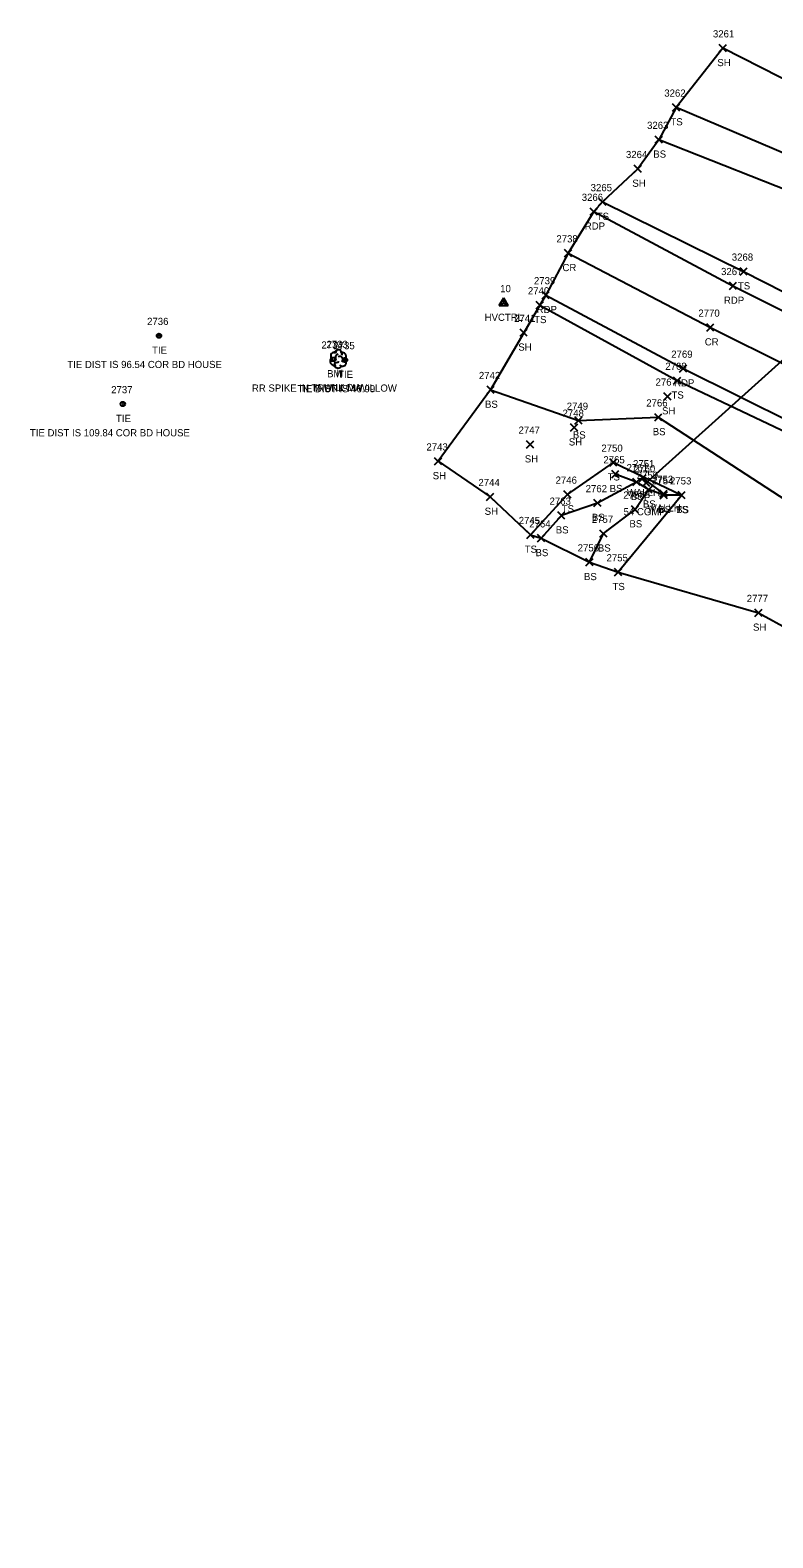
# Model space of a CAD drawing. Extents: x 1599569 to 1610055, y 642560 to 647860.
# Drawn here: x 1599569.2 to 1599776.3, y 647440.2 to 647860.2 of the extents above; entities that cross this region are included whole.
import ezdxf

# ---------------------------------------------------------------- set-up
doc = ezdxf.new("R2010")
doc.units = 0
for name, color, linetype in [('C_A', 7, 'Continuous'), ('C_C', 7, 'Continuous'), ('C_I', 7, 'Continuous'), ('CBP', 7, 'Continuous'), ('CPBM', 7, 'Continuous'), ('CPSM', 7, 'Continuous'), ('D_A', 7, 'Continuous'), ('D_C', 7, 'Continuous'), ('D_I', 7, 'Continuous'), ('D_TIC', 7, 'Continuous'), ('DCP', 7, 'Continuous'), ('DHW', 7, 'Continuous'), ('L_A', 7, 'Continuous'), ('L_C', 7, 'Continuous'), ('L_I', 7, 'Continuous'), ('L_TIC', 7, 'Continuous'), ('LELB', 7, 'Continuous'), ('LSOGP', 7, 'Continuous'), ('LTD', 7, 'Continuous'), ('P_A', 7, 'Continuous'), ('P_I', 7, 'Continuous'), ('P_TIC', 7, 'Continuous'), ('PET', 7, 'Continuous'), ('PRC', 7, 'Continuous')]:
    doc.layers.add(name, color=color, linetype=linetype)

msp = doc.modelspace()

# ---------------------------------------------------------------- linework, layer by layer
at = {"layer": 'CBP'}
for centre, radius in [((1599605.15, 647775.05), 0.625), ((1599605.15, 647775.05), 0.0833), ((1599657.03, 647768.3), 0.625), ((1599657.03, 647768.3), 0.0833), ((1599595.09, 647756.03), 0.625), ((1599595.09, 647756.03), 0.0833)]:
    msp.add_circle(centre, radius, dxfattribs=at)
at = {"layer": 'CPBM'}
for p, q in [((1599653.2, 647767.98), (1599653.2, 647768.98)), ((1599653.2, 647768.98), (1599654.2, 647768.98)), ((1599654.2, 647767.98), (1599653.2, 647767.98)), ((1599653.7, 647768.48), (1599653.7, 647768.48)), ((1599653.7, 647768.48), (1599653.7, 647768.48)), ((1599654.2, 647768.98), (1599654.2, 647767.98))]:
    msp.add_line(p, q, dxfattribs=at)
at = {"layer": 'CPSM'}
for p, q in [((1599700.01, 647783.46), (1599701.26, 647785.63)), ((1599702.51, 647783.46), (1599701.26, 647785.63)), ((1599701.26, 647784.19), (1599701.26, 647785.63)), ((1599700.01, 647783.46), (1599701.26, 647784.19)), ((1599700.01, 647783.46), (1599702.51, 647783.46)), ((1599701.26, 647784.19), (1599701.26, 647784.19)), ((1599701.26, 647784.19), (1599702.51, 647783.46))]:
    msp.add_line(p, q, dxfattribs=at)
at = {"layer": 'D_TIC'}
for points in [[(1599739.02, 647734.4), (1599741.02, 647736.4)], [(1599741.02, 647734.4), (1599739.02, 647736.4)], [(1599739.96, 647733.04), (1599741.96, 647735.04)], [(1599741.96, 647733.04), (1599739.96, 647735.04)], [(1599744.81, 647730.06), (1599746.81, 647732.06)], [(1599746.81, 647730.06), (1599744.81, 647732.06)]]:
    msp.add_lwpolyline(points, dxfattribs=at)
at = {"layer": 'DCP'}
msp.add_lwpolyline([(1599740.96, 647734.04), (1599814.69, 647800.27)], dxfattribs=at)
at = {"layer": 'DHW'}
msp.add_lwpolyline([(1599740.02, 647735.4), (1599745.81, 647731.06)], dxfattribs=at)
at = {"layer": 'L_TIC'}
for points in [[(1599761.33, 647854.15), (1599763.33, 647856.15)], [(1599763.33, 647854.15), (1599761.33, 647856.15)], [(1599748.34, 647837.65), (1599750.34, 647839.65)], [(1599750.34, 647837.65), (1599748.34, 647839.65)], [(1599743.53, 647828.66), (1599745.53, 647830.66)], [(1599745.53, 647828.66), (1599743.53, 647830.66)], [(1599737.64, 647820.54), (1599739.64, 647822.54)], [(1599739.64, 647820.54), (1599737.64, 647822.54)], [(1599727.81, 647811.31), (1599729.81, 647813.31)], [(1599729.81, 647811.31), (1599727.81, 647813.31)], [(1599767.15, 647791.96), (1599769.15, 647793.96)], [(1599769.15, 647791.96), (1599767.15, 647793.96)], [(1599710.35, 647782.57), (1599712.35, 647784.57)], [(1599712.35, 647782.57), (1599710.35, 647784.57)], [(1599705.84, 647774.9), (1599707.84, 647776.9)], [(1599707.84, 647774.9), (1599705.84, 647776.9)], [(1599748.63, 647761.55), (1599750.63, 647763.55)], [(1599750.63, 647761.55), (1599748.63, 647763.55)], [(1599696.61, 647758.98), (1599698.61, 647760.98)], [(1599698.61, 647758.98), (1599696.61, 647760.98)], [(1599745.91, 647757.15), (1599747.91, 647759.15)], [(1599747.91, 647757.15), (1599745.91, 647759.15)], [(1599721.1, 647750.43), (1599723.1, 647752.43)], [(1599723.1, 647750.43), (1599721.1, 647752.43)], [(1599743.36, 647751.34), (1599745.36, 647753.34)], [(1599745.36, 647751.34), (1599743.36, 647753.34)], [(1599719.92, 647748.48), (1599721.92, 647750.48)], [(1599721.92, 647748.48), (1599719.92, 647750.48)], [(1599707.65, 647743.76), (1599709.65, 647745.76)], [(1599709.65, 647743.76), (1599707.65, 647745.76)], [(1599681.98, 647739.08), (1599683.98, 647741.08)], [(1599683.98, 647739.08), (1599681.98, 647741.08)], [(1599730.83, 647738.74), (1599732.83, 647740.74)], [(1599732.83, 647738.74), (1599730.83, 647740.74)], [(1599731.36, 647735.5), (1599733.36, 647737.5)], [(1599733.36, 647735.5), (1599731.36, 647737.5)], [(1599737.27, 647733.3), (1599739.27, 647735.3)], [(1599739.27, 647733.3), (1599737.27, 647735.3)], [(1599737.27, 647733.3), (1599739.27, 647735.3)], [(1599739.27, 647733.3), (1599737.27, 647735.3)], [(1599696.47, 647729.17), (1599698.47, 647731.17)], [(1599698.47, 647729.17), (1599696.47, 647731.17)], [(1599718.04, 647729.84), (1599720.04, 647731.84)], [(1599720.04, 647729.84), (1599718.04, 647731.84)], [(1599740.61, 647731.19), (1599742.61, 647733.19)], [(1599742.61, 647731.19), (1599740.61, 647733.19)], [(1599740.61, 647731.19), (1599742.61, 647733.19)], [(1599742.61, 647731.19), (1599740.61, 647733.19)], [(1599744.91, 647729.65), (1599746.91, 647731.65)], [(1599746.91, 647729.65), (1599744.91, 647731.65)], [(1599749.88, 647729.63), (1599751.88, 647731.63)], [(1599751.88, 647729.63), (1599749.88, 647731.63)], [(1599749.88, 647729.63), (1599751.88, 647731.63)], [(1599751.88, 647729.63), (1599749.88, 647731.63)], [(1599716.34, 647723.98), (1599718.34, 647725.98)], [(1599718.34, 647723.98), (1599716.34, 647725.98)], [(1599726.41, 647727.46), (1599728.41, 647729.46)], [(1599728.41, 647727.46), (1599726.41, 647729.46)], [(1599736.87, 647725.67), (1599738.87, 647727.67)], [(1599738.87, 647725.67), (1599736.87, 647727.67)], [(1599707.71, 647718.6), (1599709.71, 647720.6)], [(1599709.71, 647718.6), (1599707.71, 647720.6)], [(1599710.69, 647717.65), (1599712.69, 647719.65)], [(1599712.69, 647717.65), (1599710.69, 647719.65)], [(1599728.08, 647718.93), (1599730.08, 647720.93)], [(1599730.08, 647718.93), (1599728.08, 647720.93)], [(1599724.19, 647710.97), (1599726.19, 647712.97)], [(1599726.19, 647710.97), (1599724.19, 647712.97)], [(1599732.19, 647708.2), (1599734.19, 647710.2)], [(1599734.19, 647708.2), (1599732.19, 647710.2)], [(1599771.28, 647696.88), (1599773.28, 647698.88)], [(1599773.28, 647696.88), (1599771.28, 647698.88)]]:
    msp.add_lwpolyline(points, dxfattribs=at)
at = {"layer": 'LELB'}
for points in [[(1599867.62, 647815.31), (1599840.36, 647815.31), (1599822.81, 647817.81), (1599792.8, 647820.18), (1599749.34, 647838.65)], [(1599810.07, 647804.55), (1599788.24, 647812.38), (1599744.53, 647829.66)], [(1599728.81, 647812.31), (1599768.15, 647792.96), (1599808.19, 647772.58), (1599853.49, 647751.31), (1599896.91, 647732.66), (1599944.27, 647711.3), (1599995.07, 647690.25), (1600038.53, 647673.11), (1600069.53, 647660.63), (1600111.66, 647644.91), (1600147.02, 647631.01), (1600185.01, 647616.1), (1600232.31, 647597.96), (1600265.15, 647585.19), (1600308.36, 647569.24), (1600357.09, 647550.14)], [(1599711.35, 647783.57), (1599749.63, 647762.55), (1599796.65, 647740.26), (1599833.67, 647721.94), (1599877.39, 647702.39), (1599924.86, 647682.37), (1599972.59, 647663.51), (1600011.34, 647647.51), (1600055.84, 647629.73), (1600100.47, 647612.9)], [(1599697.61, 647759.98), (1599722.1, 647751.43), (1599744.36, 647752.34), (1599789.18, 647723.21), (1599824.42, 647706.1), (1599868.39, 647681.04), (1599912.82, 647658.19), (1599958.42, 647634.17), (1599997.43, 647618.28), (1600043.89, 647603.78), (1600086.31, 647587.76), (1600138.43, 647576.08), (1600182.57, 647557.27), (1600228.03, 647536.75), (1600266.38, 647516.33), (1600313.23, 647498.51), (1600354.12, 647480.34), (1600399.45, 647460.99), (1600449.42, 647451.6), (1600497.01, 647440.19)], [(1599708.71, 647719.6), (1599719.04, 647730.84), (1599731.83, 647739.74), (1599750.88, 647730.63), (1599733.19, 647709.2)], [(1599725.19, 647711.97), (1599729.08, 647719.93), (1599737.87, 647726.67), (1599741.61, 647732.19), (1599738.27, 647734.3), (1599727.41, 647728.46), (1599717.34, 647724.98), (1599711.69, 647718.65)], [(1599738.27, 647734.3), (1599732.36, 647736.5)], [(1599750.88, 647730.63), (1599745.91, 647730.65), (1599741.61, 647732.19)]]:
    msp.add_lwpolyline(points, dxfattribs=at)
at = {"layer": 'LSOGP'}
msp.add_lwpolyline([(1599799.23, 647836.38), (1599762.33, 647855.15), (1599749.35, 647838.65), (1599744.54, 647829.66), (1599738.65, 647821.54), (1599728.81, 647812.31), (1599726.39, 647809.62), (1599719.21, 647798.06), (1599712.97, 647786.38), (1599711.35, 647783.57), (1599706.85, 647775.89), (1599697.61, 647759.98), (1599682.98, 647740.08), (1599697.47, 647730.17), (1599708.71, 647719.6), (1599711.69, 647718.65), (1599725.2, 647711.96), (1599733.19, 647709.2), (1599772.28, 647697.88), (1599807.65, 647678.52)], dxfattribs=at)
at = {"layer": 'LTD'}
msp.add_line((1599655.1, 647768.64), (1599655.1, 647768.64), dxfattribs=at)
msp.add_line((1599655.1, 647768.64), (1599655.1, 647768.64), dxfattribs=at)
msp.add_arc((1599655.14, 647770.07), 1.05, 335.5272, 180.9563, dxfattribs=at)
for centre, major_axis, ratio, start_param, end_param in [((1599654.01, 647767.93), (0.58, -1.04), 0.959034, 3.141593, 6.283185), ((1599654.31, 647769.3), (1.21, -0.51), 0.895232, 1.570796, 4.712389), ((1599654.64, 647767.89), (-0.625, -0.083), 0.423636, 0, 3.141593), ((1599654.89, 647769.09), (-0.208, -0.792), 0.645439, 3.141593, 6.283185), ((1599655.6, 647768.47), (-0.5, 0.667), 0.989748, 3.141593, 6.283185), ((1599656.1, 647767.8), (-1.09, 0.79), 0.841452, 1.570796, 4.712389), ((1599656.14, 647769.22), (-1.14, -0.48), 0.949671, 1.570796, 4.712389), ((1599655.1, 647767.14), (0.26, 1.06), 0.942809, 1.570796, 4.712389)]:
    msp.add_ellipse(centre, major_axis=major_axis, ratio=ratio, start_param=start_param, end_param=end_param, dxfattribs=at)
at = {"layer": 'P_TIC'}
for points in [[(1599725.38, 647808.62), (1599727.38, 647810.62)], [(1599727.38, 647808.62), (1599725.38, 647810.62)], [(1599718.21, 647797.05), (1599720.21, 647799.05)], [(1599720.21, 647797.05), (1599718.21, 647799.05)], [(1599764.17, 647787.95), (1599766.17, 647789.95)], [(1599766.17, 647787.95), (1599764.17, 647789.95)], [(1599711.97, 647785.38), (1599713.97, 647787.38)], [(1599713.97, 647785.38), (1599711.97, 647787.38)], [(1599757.87, 647776.36), (1599759.87, 647778.36)], [(1599759.87, 647776.36), (1599757.87, 647778.36)], [(1599750.28, 647764.92), (1599752.28, 647766.92)], [(1599752.28, 647764.92), (1599750.28, 647766.92)]]:
    msp.add_lwpolyline(points, dxfattribs=at)
at = {"layer": 'PET'}
for points in [[(1599726.38, 647809.62), (1599765.17, 647788.95), (1599807.03, 647767.98), (1599850.85, 647747.24), (1599895.21, 647727.77), (1599941.94, 647707.82), (1599994.49, 647686.81), (1600037.05, 647669.82), (1600068.7, 647657.7), (1600109.97, 647641.43), (1600146.07, 647627.29), (1600183.44, 647612.79), (1600231.32, 647594.52), (1600263.07, 647581.81), (1600307.68, 647564.32), (1600354.99, 647546.03)], [(1599712.97, 647786.38), (1599751.28, 647765.92), (1599797.63, 647742.86), (1599835.45, 647724.57), (1599878.46, 647705.28), (1599926.24, 647684.77), (1599973.4, 647665.7), (1600012.45, 647650.07), (1600057, 647632.55), (1600100.87, 647615.07)]]:
    msp.add_lwpolyline(points, dxfattribs=at)
at = {"layer": 'PRC'}
msp.add_lwpolyline([(1599719.21, 647798.05), (1599758.87, 647777.36), (1599802.99, 647755.44), (1599842.26, 647736.45), (1599884.02, 647718.08), (1599932.1, 647697.56), (1599978.21, 647679.31), (1600018.18, 647663.4), (1600061.65, 647646.14), (1600106.08, 647628.64)], dxfattribs=at)

# ---------------------------------------------------------------- texts
at = {"layer": 'C_A'}
for s, p in [('HVCTRL', (1599695.95, 647779.19)), ('TIE', (1599603.23, 647770.05)), ('BM', (1599652.02, 647763.48)), ('TIE', (1599655.11, 647763.3)), ('TIE', (1599593.17, 647751.03))]:
    msp.add_text(s, height=2, dxfattribs=at).set_placement(p)
at = {"layer": 'C_C'}
for s, p in [('TIE DIST IS 96.54 COR BD HOUSE', (1599579.59, 647766.05)), ('RR SPIKE IN TRUNK M WILLOW', (1599631.06, 647759.48)), ('TIE DIST IS 46.99', (1599643.73, 647759.3)), ('TIE DIST IS 109.84 COR BD HOUSE', (1599569.17, 647747.03))]:
    msp.add_text(s, height=2, dxfattribs=at).set_placement(p)
at = {"layer": 'C_I'}
for s, p in [('10', (1599700.27, 647787.19)), ('2736', (1599601.84, 647778.05)), ('2734', (1599650.44, 647771.48)), ('2735', (1599653.77, 647771.3)), ('2737', (1599591.83, 647759.03))]:
    msp.add_text(s, height=2, dxfattribs=at).set_placement(p)
at = {"layer": 'D_A'}
for s, p in [('WALLH', (1599735.61, 647730.4)), ('P', (1599740.34, 647729.04)), ('WALLH', (1599741.4, 647726.06))]:
    msp.add_text(s, height=2, dxfattribs=at).set_placement(p)
at = {"layer": 'D_C'}
msp.add_text('54 CGMP', height=2, dxfattribs=at).set_placement((1599734.68, 647725.04))
at = {"layer": 'D_I'}
for s, p in [('2751', (1599737.32, 647738.4)), ('2760', (1599737.56, 647737.04)), ('2752', (1599742.55, 647734.06))]:
    msp.add_text(s, height=2, dxfattribs=at).set_placement(p)
at = {"layer": 'L_A'}
for s, p in [('SH', (1599760.82, 647850.15)), ('TS', (1599747.75, 647833.65)), ('BS', (1599742.97, 647824.66)), ('SH', (1599737.13, 647816.54)), ('TS', (1599727.21, 647807.31)), ('TS', (1599766.56, 647787.96)), ('TS', (1599709.76, 647778.57)), ('SH', (1599705.33, 647770.9)), ('H', (1599654.53, 647763.64)), ('TS', (1599748.04, 647757.55)), ('BS', (1599696.05, 647754.98)), ('SH', (1599745.4, 647753.15)), ('BS', (1599720.54, 647746.43)), ('BS', (1599742.81, 647747.34)), ('SH', (1599719.41, 647744.48)), ('SH', (1599707.14, 647739.76)), ('SH', (1599681.47, 647735.08)), ('TS', (1599730.24, 647734.74)), ('BS', (1599730.8, 647731.5)), ('BS', (1599736.71, 647729.3)), ('BS', (1599736.71, 647729.3)), ('SH', (1599695.96, 647725.17)), ('TS', (1599717.45, 647725.84)), ('BS', (1599740.05, 647727.19)), ('BS', (1599740.05, 647727.19)), ('BS', (1599744.35, 647725.65)), ('TS', (1599749.28, 647725.63)), ('BS', (1599749.32, 647725.63)), ('BS', (1599715.78, 647719.98)), ('BS', (1599725.85, 647723.46)), ('BS', (1599736.31, 647721.67)), ('TS', (1599707.12, 647714.6)), ('BS', (1599710.13, 647713.65)), ('BS', (1599727.52, 647714.93)), ('BS', (1599723.64, 647706.97)), ('TS', (1599731.6, 647704.2)), ('SH', (1599770.77, 647692.88))]:
    msp.add_text(s, height=2, dxfattribs=at).set_placement(p)
at = {"layer": 'L_C'}
msp.add_text('M WILLOW', height=2, dxfattribs=at).set_placement((1599648.04, 647759.64))
at = {"layer": 'L_I'}
for s, p in [('3261', (1599759.59, 647858.15)), ('3262', (1599746.03, 647841.65)), ('3263', (1599741.23, 647832.66)), ('3264', (1599735.34, 647824.54)), ('3265', (1599725.5, 647815.31)), ('3268', (1599764.85, 647795.96)), ('2740', (1599708.01, 647786.57)), ('2741', (1599704.15, 647778.9)), ('2733', (1599651.84, 647771.64)), ('2742', (1599694.35, 647762.98)), ('2768', (1599746.32, 647765.55)), ('2767', (1599743.6, 647761.15)), ('2749', (1599718.83, 647754.43)), ('2766', (1599741, 647755.34)), ('2748', (1599717.66, 647752.48)), ('2747', (1599705.39, 647747.76)), ('2743', (1599679.72, 647743.08)), ('2750', (1599728.49, 647742.74)), ('2765', (1599729.05, 647739.5)), ('2761', (1599735.53, 647737.3)), ('2761', (1599735.53, 647737.3)), ('2744', (1599694.21, 647733.17)), ('2746', (1599715.73, 647733.84)), ('2759', (1599738.34, 647735.19)), ('2759', (1599738.34, 647735.19)), ('2754', (1599742.65, 647733.65)), ('2753', (1599747.62, 647733.63)), ('2753', (1599747.62, 647733.63)), ('2763', (1599714.04, 647727.98)), ('2762', (1599724.11, 647731.46)), ('2758', (1599734.61, 647729.67)), ('2745', (1599705.45, 647722.6)), ('2764', (1599708.38, 647721.65)), ('2757', (1599725.82, 647722.93)), ('2756', (1599721.88, 647714.97)), ('2755', (1599729.93, 647712.2)), ('2777', (1599769.02, 647700.88))]:
    msp.add_text(s, height=2, dxfattribs=at).set_placement(p)
at = {"layer": 'P_A'}
for s, p in [('RDP', (1599723.87, 647804.62)), ('CR', (1599717.64, 647793.05)), ('RDP', (1599762.65, 647783.95)), ('RDP', (1599710.45, 647781.38)), ('CR', (1599757.31, 647772.36)), ('RDP', (1599748.77, 647760.92))]:
    msp.add_text(s, height=2, dxfattribs=at).set_placement(p)
at = {"layer": 'P_I'}
for s, p in [('3266', (1599723.02, 647812.62)), ('2738', (1599715.95, 647801.05)), ('3267', (1599761.86, 647791.95)), ('2739', (1599709.7, 647789.38)), ('2770', (1599755.53, 647780.36)), ('2769', (1599747.97, 647768.92))]:
    msp.add_text(s, height=2, dxfattribs=at).set_placement(p)

doc.saveas('drawing.dxf')
